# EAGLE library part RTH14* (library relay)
Power PCB Relay 105°C 16A SCHRACK 1 pole 16 A, high-temperature version Source: http://www.schrack.com/.. 5831.pdf
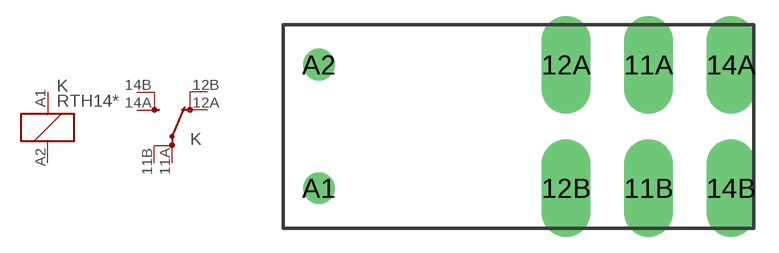
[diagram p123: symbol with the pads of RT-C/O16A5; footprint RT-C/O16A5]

Designator prefix K; gates 1=K 2=U-X2

## RTH14009 (OC_FARNELL: unknown; OC_NEWARK: unknown), RTH14012 (MPN: RTH14012; OC_FARNELL: 1629018; OC_NEWARK: 03P2408), RTH14024 (MF: TYCO ELECTRONICS; MPN: 7-1415025-1; OC_FARNELL: unknown; OC_NEWARK: 16H4440)  [RT-C/O16A5]
11A  2:PA  pas
11B  2:PB  pas
12A  2:OA  pas
12B  2:OB  pas
14A  2:SA  pas
14B  2:SB  pas
A1  1:1  pas
A2  1:2  pas

## Footprint RT-C/O16A5 (pad centres in mm)
Power PCB Relay 1 pole 12 / 16 A, DC- or AC-coil SCHRACK 16 A, pinning 5mm Source: http://www.schrack.com/.. 5819.pdf
drill 1.3 pad 3 long: 11A 7.56,3.78; 11B 7.56,-3.78; 12A 2.52,3.78; 12B 2.52,-3.78; 14A 12.6,3.78; 14B 12.6,-3.78
drill 1.3 round: A1 -12.6,-3.78; A2 -12.6,3.78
